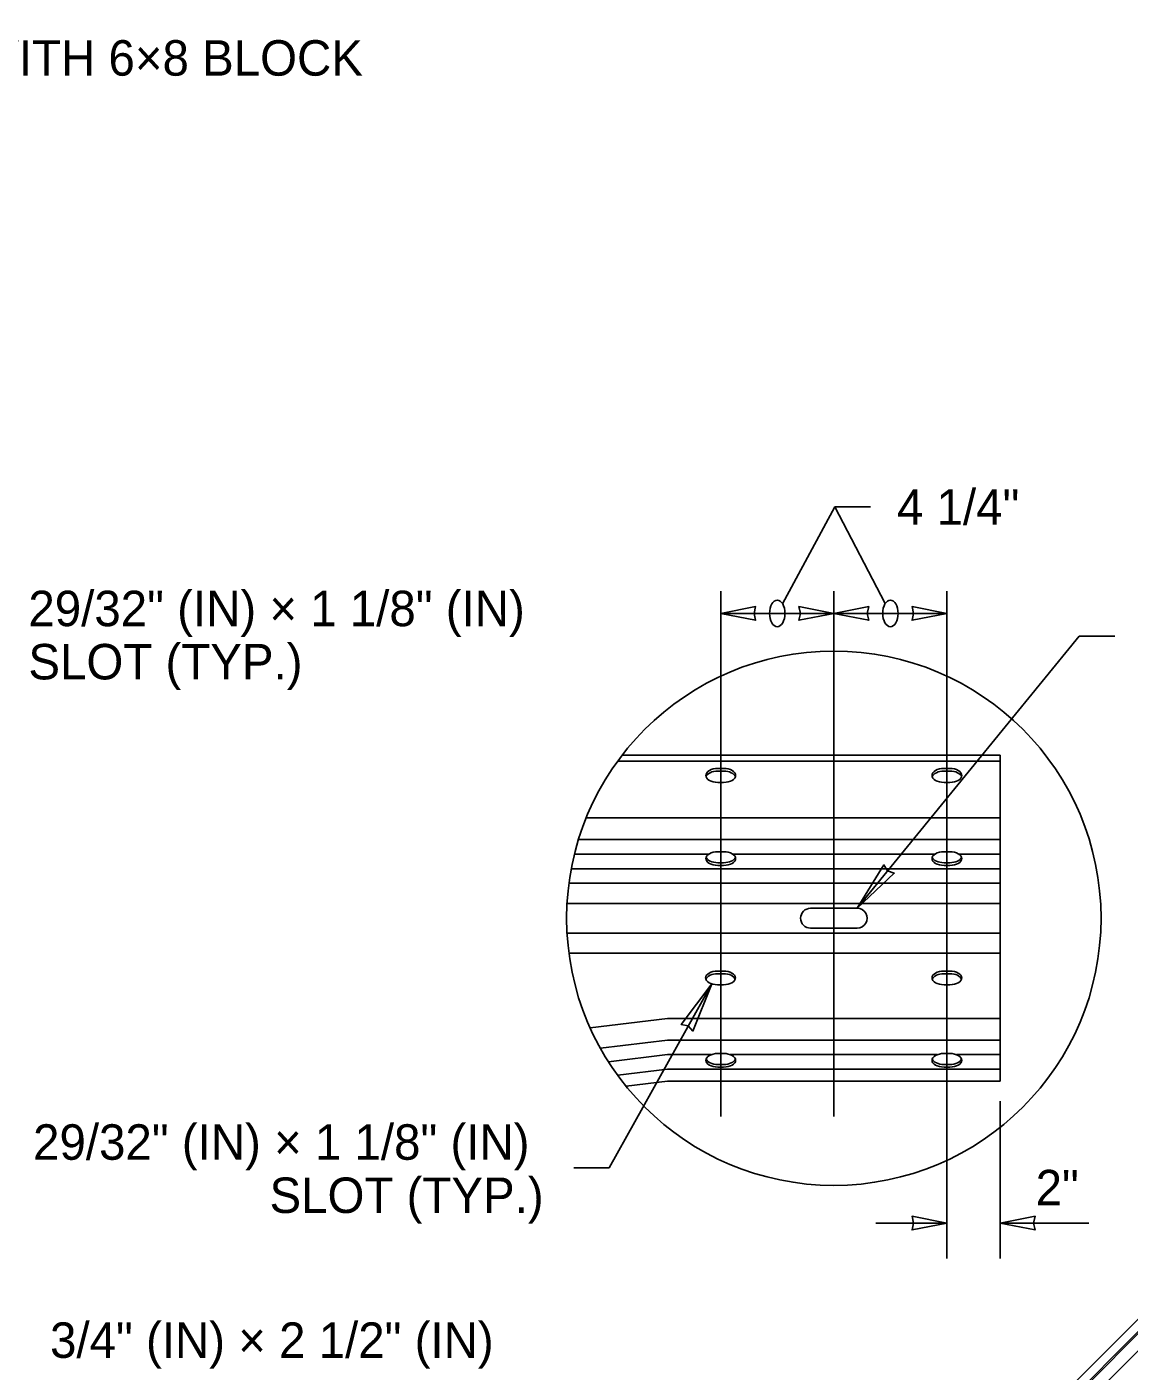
# Model space of a CAD drawing. Extents: x 34446 to 262144, y 33903 to 262144.
# Drawn here: x 100218 to 100715, y 100311 to 100918 of the extents above; entities that cross this region are included whole.
import ezdxf

# ---------------------------------------------------------------- set-up
doc = ezdxf.new("R2010")
doc.units = 0
for name, color, linetype in [('Level 12', 7, 'Continuous'), ('Level 15', 7, 'Continuous'), ('Level 20', 7, 'Continuous'), ('Level 5', 7, 'Continuous'), ('Level 9', 7, 'Continuous')]:
    doc.layers.add(name, color=color, linetype=linetype)

msp = doc.modelspace()

# ---------------------------------------------------------------- linework, layer by layer
at = {"layer": 'Level 12'}
for p, q in [((100486.79193419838, 100589.1902009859), (100657.2801197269, 100589.1902009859)), ((100657.2801197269, 100442.19020096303), (100657.2801197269, 100589.1902009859)), ((100507.28013472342, 100442.19020096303), (100488.58274157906, 100439.92069786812)), ((100657.2801197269, 100442.19020096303), (100507.28013472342, 100442.19020096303))]:
    msp.add_line(p, q, dxfattribs=at)
for points in [[(100592.78022367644, 100520.16745105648), (100571.78022577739, 100520.16745105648)], [(100571.78022577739, 100511.21313633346), (100592.78022367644, 100511.21313633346)]]:
    msp.add_lwpolyline(points, dxfattribs=at)
for centre, start_param, end_param in [((100571.78022577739, 100515.69029369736), 1.5707963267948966, 4.71238898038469), ((100592.78022367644, 100515.69029369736), 4.712388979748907, 7.853981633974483)]:
    msp.add_ellipse(centre, major_axis=(4.499999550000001, 0), ratio=0.9949239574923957, start_param=start_param, end_param=end_param, dxfattribs=at)
at = {"layer": 'Level 15'}
for p, q in [((100582.78022472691, 100701.1902009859), (100559.1503995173, 100657.56590828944)), ((100598.78022472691, 100701.1902009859), (100582.78022472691, 100701.1902009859)), ((100582.78022472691, 100701.1902009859), (100605.45986631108, 100657.64528914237)), ((100531.28022472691, 100426.19020096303), (100531.28022472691, 100663.1902009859)), ((100582.28022472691, 100426.19020096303), (100582.28022472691, 100663.1902009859)), ((100633.28022472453, 100663.1902009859), (100633.28022472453, 100362.19020096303)), ((100582.28022472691, 100653.1902009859), (100531.2802247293, 100653.1902009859)), ((100582.28022472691, 100653.1902009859), (100633.28022472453, 100653.1902009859)), ((100592.78022367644, 100520.16745105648), (100692.9969177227, 100642.98191339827)), ((100692.9969177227, 100642.98191339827), (100708.9969177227, 100642.98191339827)), ((100481.02183043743, 100403.17396454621), (100527.21752607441, 100486.16605296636)), ((100657.2801197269, 100433.24254960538), (100657.2801197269, 100362.19020096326)), ((100481.02183043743, 100403.17396454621), (100465.02183043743, 100403.17396454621)), ((100633.28022472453, 100378.19020096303), (100601.28022472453, 100378.19020096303)), ((100697.32914514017, 100378.19020096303), (100657.2801197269, 100378.19020096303))]:
    msp.add_line(p, q, dxfattribs=at)
for points in [[(100531.2802247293, 100653.1902009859), (100547.0052247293, 100650.10620098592), (100546.2772247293, 100653.1902009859), (100547.0052247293, 100656.2742009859)], [(100582.28022472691, 100653.1902009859), (100566.55522472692, 100650.10620098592), (100567.28322472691, 100653.1902009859), (100566.55522472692, 100656.2742009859)], [(100582.28022472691, 100653.1902009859), (100598.00522472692, 100650.10620098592), (100597.27722472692, 100653.1902009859), (100598.00522472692, 100656.2742009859)], [(100633.28022472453, 100653.1902009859), (100617.55522472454, 100650.10620098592), (100618.28322472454, 100653.1902009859), (100617.55522472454, 100656.2742009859)], [(100592.78022367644, 100520.16745105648), (100609.50021192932, 100535.99513120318), (100606.51810887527, 100537.0592845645), (100604.86922363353, 100539.76273633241)], [(100527.21752607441, 100486.16605296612), (100513.47786400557, 100467.69187768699), (100516.59881332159, 100467.15798971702), (100518.68925053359, 100464.77943001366)], [(100633.28022472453, 100378.19020096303), (100617.55522472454, 100375.10620096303), (100618.28322472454, 100378.19020096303), (100617.55522472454, 100381.27420096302)], [(100657.2801197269, 100378.19020096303), (100673.00511972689, 100375.10620096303), (100672.2771197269, 100378.19020096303), (100673.00511972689, 100381.27420096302)]]:
    msp.add_lwpolyline(points, close=True, dxfattribs=at)
msp.add_circle((100582.2802247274, 100515.6902936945), 120.5, dxfattribs=at)
for centre in [(100556.7802247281, 100653.1902009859), (100607.78022472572, 100653.1902009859)]:
    msp.add_ellipse(centre, major_axis=(-9.648735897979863e-16, -5.999999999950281), ratio=0.5773502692, dxfattribs=at)
at = {"layer": 'Level 5'}
msp.add_spline([(100965.33493063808, 100576.21973024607), (100979.73117748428, 100581.07419127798), (100976.64599230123, 100587.06308016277), (100980.63858489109, 100590.14826534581), (100978.82377007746, 100594.86678386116), (100978.82377007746, 100594.86678386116), (100972.34760629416, 100605.2602740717)], degree=3, dxfattribs=at)
at = {"layer": 'Level 9'}
for p, q in [((100484.80685996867, 100586.53655797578), (100657.2801197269, 100586.53655797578)), ((100494.88996876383, 100586.53655797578), (100657.2801197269, 100586.53655797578)), ((100532.58606211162, 100583.27795842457), (100529.97438734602, 100583.27795842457)), ((100532.58606211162, 100582.07033899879), (100529.97438734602, 100582.07033899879)), ((100634.58606210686, 100583.27796697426), (100631.97438734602, 100583.27796697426)), ((100634.58606210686, 100582.07034755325), (100631.97438734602, 100582.07034755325)), ((100529.97438734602, 100576.92077891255), (100532.58606211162, 100576.92077891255)), ((100631.97438734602, 100576.92078746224), (100634.58606210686, 100576.92078746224)), ((100470.58901739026, 100560.9155543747), (100657.2801197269, 100560.9155543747)), ((100467.13643430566, 100551.21715011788), (100657.2801197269, 100551.21715011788)), ((100465.3069240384, 100544.62983283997), (100525.92212711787, 100544.62983283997)), ((100529.97438734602, 100545.6673307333), (100532.58606210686, 100545.6673307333)), ((100536.63832233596, 100544.62983283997), (100627.92211380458, 100544.62983283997)), ((100634.58606210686, 100545.66733928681), (100631.97438734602, 100545.66733928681)), ((100638.63833564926, 100544.62983283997), (100657.2801197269, 100544.62983283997)), ((100463.87149119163, 100538.04251556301), (100657.2801197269, 100538.04251556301)), ((100532.58606210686, 100540.72682209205), (100529.97438734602, 100540.72682209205)), ((100532.58606210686, 100539.51885959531), (100529.97438734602, 100539.51885959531)), ((100631.97438734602, 100540.72683064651), (100634.58606210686, 100540.72683064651)), ((100631.97438734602, 100539.51886815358), (100634.58606210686, 100539.51886815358)), ((100462.81592972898, 100531.45519840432), (100657.2801197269, 100531.45519840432)), ((100461.9652328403, 100522.36507662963), (100657.2801197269, 100522.36507662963)), ((100461.96523928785, 100509.0153945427), (100657.2801197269, 100509.0153945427)), ((100462.81594508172, 100499.92527264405), (100657.2801197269, 100499.92527264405)), ((100532.48950341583, 100491.86172780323), (100529.87782865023, 100491.86172780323)), ((100532.48950341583, 100490.65376531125), (100529.87782865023, 100490.65376531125)), ((100634.58606210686, 100491.86171923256), (100631.97438734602, 100491.86171923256)), ((100634.58606210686, 100490.6537567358), (100631.97438734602, 100490.6537567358)), ((100529.87782865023, 100485.71325667), (100532.48950341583, 100485.71325667)), ((100631.97438734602, 100485.71324809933), (100634.58606210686, 100485.71324809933)), ((100472.40415299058, 100466.21809079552), (100507.28013472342, 100470.46491679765)), ((100507.28013472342, 100470.46491679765), (100657.2801197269, 100470.46491679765)), ((100507.28013472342, 100470.46491679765), (100657.2801197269, 100470.46491679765)), ((100477.00831458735, 100457.0551938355), (100507.28013472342, 100460.76651253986)), ((100507.28013472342, 100460.76651253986), (100657.2801197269, 100460.76651253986)), ((100507.28013472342, 100460.76651253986), (100657.2801197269, 100460.76651253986)), ((100480.66381900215, 100450.92644507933), (100507.28013472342, 100454.17919526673)), ((100507.28013472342, 100454.17919526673), (100527.02443560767, 100454.17919526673)), ((100529.97438734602, 100454.6764564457), (100532.58606210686, 100454.6764564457)), ((100535.53601384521, 100454.17919526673), (100629.02441246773, 100454.17919526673)), ((100634.58606210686, 100454.67646500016), (100631.97438734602, 100454.67646500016)), ((100637.53603698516, 100454.17919526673), (100657.2801197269, 100454.17919526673)), ((100484.80005017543, 100444.85339956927), (100507.28013472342, 100447.59187798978)), ((100507.28013472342, 100447.59187798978), (100657.2801197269, 100447.59187798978)), ((100507.28013472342, 100447.59187798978), (100657.2801197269, 100447.59187798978)), ((100532.58606210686, 100449.73594780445), (100529.97438734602, 100449.73594780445)), ((100532.58606210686, 100448.5279853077), (100529.97438734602, 100448.5279853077)), ((100631.97438734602, 100449.73595635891), (100634.58606210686, 100449.73595635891)), ((100631.97438734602, 100448.52799386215), (100634.58606210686, 100448.52799386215))]:
    msp.add_line(p, q, dxfattribs=at)
for centre, major_axis, ratio, start_param, end_param in [((100529.97438734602, 100580.09936866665), (-5.409897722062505, 6.625213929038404e-16), 0.5875508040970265, 4.71238898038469, 7.853981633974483), ((100529.97438734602, 100578.89174924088), (-5.409897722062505, 6.625213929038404e-16), 0.5875508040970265, 4.71238898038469, 6.092062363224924), ((100532.58606211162, 100580.09936866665), (-5.409897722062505, 6.625213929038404e-16), 0.5875508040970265, 1.5707963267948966, 4.71238898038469), ((100532.58606211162, 100578.89174924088), (-5.409897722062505, 6.625213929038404e-16), 0.5875508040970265, 3.332715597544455, 4.71238898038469), ((100631.97438734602, 100580.09937721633), (-5.409897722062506, 6.625213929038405e-16), 0.5875508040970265, 4.71238898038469, 7.853981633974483), ((100631.97438734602, 100578.89175779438), (-5.409897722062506, 6.625213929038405e-16), 0.5875508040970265, 4.71238898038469, 6.0920623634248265), ((100634.58606210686, 100580.09937721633), (-5.409897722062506, 6.625213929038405e-16), 0.5875508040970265, 1.5707963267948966, 4.71238898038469), ((100634.58606210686, 100578.89175779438), (-5.409897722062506, 6.625213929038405e-16), 0.5875508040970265, 3.3327155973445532, 4.71238898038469), ((100529.97438734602, 100542.5930951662), (-5.409897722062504, 6.625213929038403e-16), 0.5682613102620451, 4.71238898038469, 7.853981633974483), ((100529.97438734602, 100543.80105765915), (-5.409897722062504, 6.625213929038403e-16), 0.5682613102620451, 0.1977518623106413, 1.5707963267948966), ((100532.58606210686, 100542.5930951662), (-5.409897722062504, 6.625213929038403e-16), 0.5682613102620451, 1.5707963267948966, 4.71238898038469), ((100532.58606210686, 100543.80105765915), (-5.409897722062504, 6.625213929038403e-16), 0.5682613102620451, 1.5707963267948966, 2.943840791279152), ((100631.97438734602, 100542.59310372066), (-5.409897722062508, 6.625213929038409e-16), 0.5682613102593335, 4.71238898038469, 7.853981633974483), ((100631.97438734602, 100543.80106621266), (-5.409897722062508, 6.625213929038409e-16), 0.5682613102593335, 0.1977518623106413, 1.5707963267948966), ((100634.58606210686, 100542.59310372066), (-5.409897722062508, 6.625213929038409e-16), 0.5682613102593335, 1.5707963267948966, 4.71238898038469), ((100634.58606210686, 100543.80106621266), (-5.409897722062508, 6.625213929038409e-16), 0.5682613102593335, 1.5707963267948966, 2.943840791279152), ((100529.87782865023, 100488.7874922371), (5.409897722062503, 0), 0.5682613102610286, 1.5707963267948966, 4.71238898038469), ((100529.87782865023, 100487.57952973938), (5.409897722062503, 0), 0.5682613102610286, 1.5707963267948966, 2.9438407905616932), ((100532.48950341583, 100488.7874922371), (5.409897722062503, 0), 0.5682613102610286, 4.71238898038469, 7.853981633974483), ((100532.48950341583, 100487.57952973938), (5.409897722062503, 0), 0.5682613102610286, 0.1977518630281, 1.5707963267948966), ((100631.97438734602, 100488.78748366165), (5.409897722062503, 0), 0.5682613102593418, 1.5707963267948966, 4.71238898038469), ((100631.97438734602, 100487.57952116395), (5.409897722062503, 0), 0.5682613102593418, 1.5707963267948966, 2.9438407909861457), ((100634.58606210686, 100488.78748366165), (5.409897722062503, 0), 0.5682613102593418, 4.71238898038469, 7.853981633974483), ((100634.58606210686, 100487.57952116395), (5.409897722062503, 0), 0.5682613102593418, 0.19775186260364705, 1.5707963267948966), ((100529.97438734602, 100451.6022208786), (-5.409897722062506, -4.142433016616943e-15), 0.5682613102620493, 4.71238898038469, 7.853981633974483), ((100529.97438734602, 100452.81018337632), (-5.409897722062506, -4.142433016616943e-15), 0.5682613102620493, 0.1977518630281, 1.5707963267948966), ((100532.58606210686, 100451.6022208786), (-5.409897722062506, -4.142433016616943e-15), 0.5682613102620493, 1.5707963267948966, 4.71238898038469), ((100532.58606210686, 100452.81018337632), (-5.409897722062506, -4.142433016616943e-15), 0.5682613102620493, 1.5707963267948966, 2.9438407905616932), ((100631.97438734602, 100451.60222943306), (-5.409897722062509, -4.1424330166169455e-15), 0.568261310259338, 4.71238898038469, 7.853981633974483), ((100631.97438734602, 100452.81019192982), (-5.409897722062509, -4.1424330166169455e-15), 0.568261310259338, 0.19775186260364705, 1.5707963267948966), ((100634.58606210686, 100451.60222943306), (-5.409897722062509, -4.1424330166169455e-15), 0.568261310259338, 1.5707963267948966, 4.71238898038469), ((100634.58606210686, 100452.81019192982), (-5.409897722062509, -4.1424330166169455e-15), 0.568261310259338, 1.5707963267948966, 2.9438407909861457)]:
    msp.add_ellipse(centre, major_axis=major_axis, ratio=ratio, start_param=start_param, end_param=end_param, dxfattribs=at)

# ---------------------------------------------------------------- texts
at = {"layer": 'Level 20'}
for s, p in [('WITH 6×8 BLOCK', (100194.52825228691, 100895.71120916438)), ('29/32" (IN) × 1 1/8" (IN)', (100219.02848967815, 100647.4068193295)), ('SLOT (TYP.)', (100219.02848967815, 100623.4068193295)), ('29/32" (IN) × 1 1/8" (IN)', (100221.1455580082, 100406.74905861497)), ('SLOT (TYP.)', (100327.7725111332, 100382.74905861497)), ('3/4" (IN) × 2 1/2" (IN)', (100228.78636627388, 100317.40517700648))]:
    msp.add_text(s, height=16, dxfattribs=at).set_placement(p)
for s, height, p in [('4 1/4" ', 16, (100610.78022472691, 100693.1902009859)), ('2"', 15.999999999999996, (100673.2801197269, 100386.19020096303))]:
    msp.add_text(s, height=height, rotation=360, dxfattribs=at).set_placement(p)

doc.saveas('drawing.dxf')
